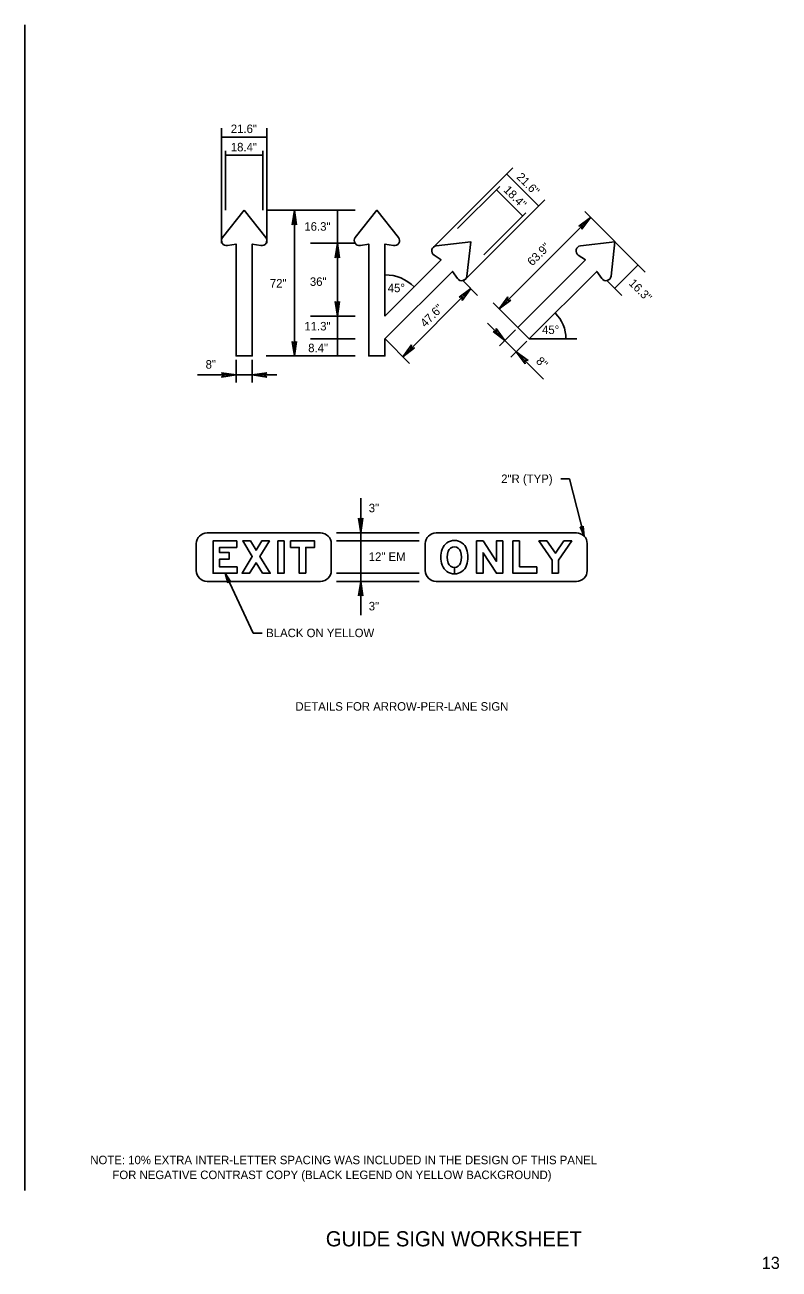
# Model space of a CAD drawing. Extents: x 531799 to 532094, y 1531149 to 1533620.
# Drawn here: x 531879.4 to 531932.2, y 1531151.4 to 1531238.5 of the extents above; entities that cross this region are included whole.
import ezdxf

# ---------------------------------------------------------------- set-up
doc = ezdxf.new("R2010")
doc.units = 0
for name, color, linetype in [('GSBWFill', 7, 'Continuous'), ('GSColorFill', 7, 'Continuous'), ('GSDims', 7, 'Continuous'), ('GSOutline', 7, 'Continuous'), ('LeaderLine_dp', 7, 'Continuous'), ('SheetBorder_dp', 7, 'Continuous'), ('SignPanel', 7, 'Continuous'), ('TextLabel', 7, 'Continuous'), ('TextMisc', 7, 'Continuous'), ('TextShtNo', 7, 'Continuous')]:
    doc.layers.add(name, color=color, linetype=linetype)

msp = doc.modelspace()

# ---------------------------------------------------------------- linework, layer by layer
at = {"layer": 'GSBWFill'}
for p, q in [((531892.157, 1531202.947), (531900.088, 1531202.947)), ((531917.996, 1531202.947), (531908.176, 1531202.947)), ((531891.401, 1531200.304), (531891.401, 1531202.192)), ((531900.844, 1531202.192), (531900.844, 1531200.304)), ((531907.421, 1531202.192), (531907.421, 1531200.304)), ((531918.751, 1531200.304), (531918.751, 1531202.192)), ((531909.458, 1531200.075), (531909.458, 1531200.528)), ((531909.458, 1531200.528), (531909.458, 1531200.075)), ((531900.088, 1531199.548), (531892.157, 1531199.548)), ((531908.176, 1531199.548), (531917.996, 1531199.548))]:
    msp.add_line(p, q, dxfattribs=at)
for points in [[(531894.227, 1531202.381), (531894.227, 1531201.928), (531893.026, 1531201.928), (531893.026, 1531201.565), (531893.705, 1531201.565), (531893.705, 1531201.112), (531893.026, 1531201.112), (531893.026, 1531200.568), (531894.249, 1531200.568), (531894.249, 1531200.115), (531892.572, 1531200.115), (531892.572, 1531202.381)], [(531896.039, 1531200.115), (531895.584, 1531200.859), (531895.129, 1531200.115), (531894.598, 1531200.115), (531895.319, 1531201.294), (531894.655, 1531202.381), (531895.186, 1531202.381), (531895.584, 1531201.729), (531895.982, 1531202.381), (531896.513, 1531202.381), (531895.85, 1531201.294), (531896.57, 1531200.115)], [(531897.094, 1531202.381), (531897.547, 1531202.381), (531897.547, 1531200.115), (531897.094, 1531200.115)], [(531899.061, 1531200.115), (531898.608, 1531200.115), (531898.608, 1531201.928), (531897.996, 1531201.928), (531897.996, 1531202.381), (531899.673, 1531202.381), (531899.673, 1531201.928), (531899.061, 1531201.928)], [(531911.012, 1531202.381), (531911.465, 1531202.381), (531912.394, 1531200.953), (531912.394, 1531202.381), (531912.847, 1531202.381), (531912.847, 1531200.115), (531912.399, 1531200.115), (531911.465, 1531201.55), (531911.465, 1531200.115), (531911.012, 1531200.115)], [(531914.003, 1531200.568), (531915.226, 1531200.568), (531915.226, 1531200.115), (531913.549, 1531200.115), (531913.549, 1531202.381), (531914.003, 1531202.381)], [(531916.748, 1531200.115), (531916.295, 1531200.115), (531916.295, 1531201.044), (531915.377, 1531202.381), (531915.926, 1531202.381), (531916.521, 1531201.515), (531917.116, 1531202.381), (531917.666, 1531202.381), (531916.748, 1531201.044)]]:
    msp.add_lwpolyline(points, close=True, dxfattribs=at)
for centre, radius, start, end in [((531892.157, 1531202.192), 0.755, 90, 180), ((531900.088, 1531202.192), 0.755, 0, 90), ((531908.176, 1531202.192), 0.755, 90, 180), ((531917.996, 1531202.192), 0.755, 0, 90), ((531909.458, 1531201.506), 0.906, 19.60625, 160.39375), ((531910.195, 1531201.244), 1.688, 160.39375, 199.60625), ((531910.195, 1531201.244), 1.235, 160.39375, 199.60625), ((531909.458, 1531201.506), 0.453, 19.60625, 160.39375), ((531908.722, 1531201.244), 1.235, 340.39375, 19.60625), ((531908.722, 1531201.244), 1.688, 340.39375, 19.60625), ((531892.157, 1531200.304), 0.755, 180, 270), ((531900.088, 1531200.304), 0.755, 270, 0), ((531908.176, 1531200.304), 0.755, 180, 270), ((531909.458, 1531200.982), 0.906, 199.60625, 270), ((531909.458, 1531200.982), 0.453, 199.60625, 270), ((531909.458, 1531200.982), 0.453, 270.01433, 340.39375), ((531909.458, 1531200.982), 0.906, 270.00716, 340.39375), ((531917.996, 1531200.304), 0.755, 270, 0)]:
    msp.add_arc(centre, radius, start, end, dxfattribs=at)
at = {"layer": 'GSColorFill'}
for p, q in [((531909.458, 1531200.075), (531909.458, 1531200.528)), ((531909.458, 1531200.528), (531909.458, 1531200.075))]:
    msp.add_line(p, q, dxfattribs=at)
for points in [[(531894.227, 1531202.381), (531894.227, 1531201.928), (531893.026, 1531201.928), (531893.026, 1531201.565), (531893.705, 1531201.565), (531893.705, 1531201.112), (531893.026, 1531201.112), (531893.026, 1531200.568), (531894.249, 1531200.568), (531894.249, 1531200.115), (531892.572, 1531200.115), (531892.572, 1531202.381)], [(531896.039, 1531200.115), (531895.584, 1531200.859), (531895.129, 1531200.115), (531894.598, 1531200.115), (531895.319, 1531201.294), (531894.655, 1531202.381), (531895.186, 1531202.381), (531895.584, 1531201.729), (531895.982, 1531202.381), (531896.513, 1531202.381), (531895.85, 1531201.294), (531896.57, 1531200.115)], [(531897.094, 1531202.381), (531897.547, 1531202.381), (531897.547, 1531200.115), (531897.094, 1531200.115)], [(531899.061, 1531200.115), (531898.608, 1531200.115), (531898.608, 1531201.928), (531897.996, 1531201.928), (531897.996, 1531202.381), (531899.673, 1531202.381), (531899.673, 1531201.928), (531899.061, 1531201.928)], [(531911.012, 1531202.381), (531911.465, 1531202.381), (531912.394, 1531200.953), (531912.394, 1531202.381), (531912.847, 1531202.381), (531912.847, 1531200.115), (531912.399, 1531200.115), (531911.465, 1531201.55), (531911.465, 1531200.115), (531911.012, 1531200.115)], [(531914.003, 1531200.568), (531915.226, 1531200.568), (531915.226, 1531200.115), (531913.549, 1531200.115), (531913.549, 1531202.381), (531914.003, 1531202.381)], [(531916.748, 1531200.115), (531916.295, 1531200.115), (531916.295, 1531201.044), (531915.377, 1531202.381), (531915.926, 1531202.381), (531916.521, 1531201.515), (531917.116, 1531202.381), (531917.666, 1531202.381), (531916.748, 1531201.044)]]:
    msp.add_lwpolyline(points, close=True, dxfattribs=at)
for centre, radius, start, end in [((531909.458, 1531201.506), 0.906, 19.60625, 160.39375), ((531910.195, 1531201.244), 1.688, 160.39375, 199.60625), ((531910.195, 1531201.244), 1.235, 160.39375, 199.60625), ((531909.458, 1531201.506), 0.453, 19.60625, 160.39375), ((531908.722, 1531201.244), 1.235, 340.39375, 19.60625), ((531908.722, 1531201.244), 1.688, 340.39375, 19.60625), ((531909.458, 1531200.982), 0.906, 199.60625, 270), ((531909.458, 1531200.982), 0.453, 199.60625, 270), ((531909.458, 1531200.982), 0.453, 270.01433, 340.39375), ((531909.458, 1531200.982), 0.906, 270.00716, 340.39375)]:
    msp.add_arc(centre, radius, start, end, dxfattribs=at)
at = {"layer": 'GSOutline'}
for points in [[(531894.227, 1531202.381), (531894.227, 1531201.928), (531893.026, 1531201.928), (531893.026, 1531201.565), (531893.705, 1531201.565), (531893.705, 1531201.112), (531893.026, 1531201.112), (531893.026, 1531200.568), (531894.249, 1531200.568), (531894.249, 1531200.115), (531892.572, 1531200.115), (531892.572, 1531202.381)], [(531896.039, 1531200.115), (531895.584, 1531200.859), (531895.129, 1531200.115), (531894.598, 1531200.115), (531895.319, 1531201.294), (531894.655, 1531202.381), (531895.186, 1531202.381), (531895.584, 1531201.729), (531895.982, 1531202.381), (531896.513, 1531202.381), (531895.85, 1531201.294), (531896.57, 1531200.115)], [(531897.094, 1531202.381), (531897.547, 1531202.381), (531897.547, 1531200.115), (531897.094, 1531200.115)], [(531899.061, 1531200.115), (531898.608, 1531200.115), (531898.608, 1531201.928), (531897.996, 1531201.928), (531897.996, 1531202.381), (531899.673, 1531202.381), (531899.673, 1531201.928), (531899.061, 1531201.928)], [(531911.012, 1531202.381), (531911.465, 1531202.381), (531912.394, 1531200.953), (531912.394, 1531202.381), (531912.847, 1531202.381), (531912.847, 1531200.115), (531912.399, 1531200.115), (531911.465, 1531201.55), (531911.465, 1531200.115), (531911.012, 1531200.115)], [(531914.003, 1531200.568), (531915.226, 1531200.568), (531915.226, 1531200.115), (531913.549, 1531200.115), (531913.549, 1531202.381), (531914.003, 1531202.381)], [(531916.748, 1531200.115), (531916.295, 1531200.115), (531916.295, 1531201.044), (531915.377, 1531202.381), (531915.926, 1531202.381), (531916.521, 1531201.515), (531917.116, 1531202.381), (531917.666, 1531202.381), (531916.748, 1531201.044)]]:
    msp.add_lwpolyline(points, close=True, dxfattribs=at)
for centre, radius, start, end in [((531909.458, 1531201.506), 0.906, 19.60625, 160.39375), ((531910.195, 1531201.244), 1.688, 160.39375, 199.60625), ((531910.195, 1531201.244), 1.235, 160.39375, 199.60625), ((531909.458, 1531201.506), 0.453, 19.60625, 160.39375), ((531908.722, 1531201.244), 1.235, 340.39375, 19.60625), ((531908.722, 1531201.244), 1.688, 340.39375, 19.60625), ((531909.458, 1531200.982), 0.906, 199.60625, 340.39375), ((531909.458, 1531200.982), 0.453, 199.60625, 340.39375)]:
    msp.add_arc(centre, radius, start, end, dxfattribs=at)
at = {"layer": 'LeaderLine_dp'}
for p, q in [((531893.165, 1531223.222), (531893.165, 1531231.279)), ((531896.334, 1531223.222), (531896.334, 1531231.279)), ((531893.165, 1531230.656), (531896.334, 1531230.656)), ((531893.447, 1531225.53), (531893.447, 1531229.697)), ((531893.447, 1531229.376), (531896.053, 1531229.376)), ((531896.053, 1531225.53), (531896.053, 1531229.697)), ((531907.848, 1531222.811), (531913.545, 1531228.509)), ((531913.105, 1531228.068), (531915.346, 1531225.827)), ((531909.68, 1531224.245), (531912.626, 1531227.191)), ((531912.399, 1531226.964), (531914.241, 1531225.121)), ((531902.506, 1531225.53), (531896.334, 1531225.53)), ((531898.107, 1531224.511), (531898.26, 1531225.53)), ((531898.26, 1531215.333), (531898.26, 1531225.53)), ((531898.26, 1531225.53), (531898.413, 1531224.511)), ((531901.268, 1531223.222), (531901.268, 1531225.53)), ((531910.089, 1531220.57), (531915.787, 1531226.268)), ((531898.26, 1531224.715), (531898.107, 1531224.511)), ((531898.413, 1531224.511), (531898.26, 1531224.715)), ((531911.522, 1531222.402), (531914.468, 1531225.348)), ((531912.584, 1531218.633), (531918.984, 1531225.032)), ((531918.155, 1531224.419), (531918.984, 1531225.032)), ((531918.984, 1531225.032), (531918.371, 1531224.203)), ((531918.578, 1531225.438), (531922.811, 1531221.205)), ((531918.407, 1531224.455), (531918.155, 1531224.419)), ((531918.371, 1531224.203), (531918.407, 1531224.455)), ((531902.506, 1531223.222), (531899.393, 1531223.222)), ((531901.115, 1531222.202), (531901.268, 1531223.222)), ((531901.268, 1531218.123), (531901.268, 1531223.222)), ((531901.268, 1531223.222), (531901.421, 1531222.202)), ((531901.268, 1531222.406), (531901.115, 1531222.202)), ((531901.421, 1531222.202), (531901.268, 1531222.406)), ((531920.672, 1531220.079), (531922.305, 1531221.711)), ((531910.089, 1531220.57), (531911.086, 1531219.573)), ((531920.181, 1531220.57), (531921.178, 1531219.573)), ((531905.846, 1531215.28), (531910.613, 1531220.047)), ((531909.783, 1531219.434), (531910.613, 1531220.047)), ((531910.036, 1531219.47), (531909.783, 1531219.434)), ((531910.613, 1531220.047), (531910, 1531219.218)), ((531910, 1531219.218), (531910.036, 1531219.47)), ((531912.584, 1531218.633), (531913.197, 1531219.462)), ((531913.197, 1531219.462), (531913.161, 1531219.209)), ((531901.268, 1531218.123), (531901.115, 1531219.143)), ((531901.115, 1531219.143), (531901.268, 1531218.939)), ((531901.268, 1531218.939), (531901.421, 1531219.143)), ((531901.421, 1531219.143), (531901.268, 1531218.123)), ((531912.179, 1531219.038), (531913.894, 1531217.323)), ((531913.414, 1531219.246), (531912.584, 1531218.633)), ((531913.161, 1531219.209), (531913.414, 1531219.246)), ((531902.506, 1531218.123), (531899.393, 1531218.123)), ((531901.268, 1531215.333), (531901.268, 1531218.123)), ((531911.777, 1531217.631), (531912.989, 1531216.418)), ((531912.412, 1531216.995), (531912.16, 1531217.031)), ((531912.16, 1531217.031), (531912.989, 1531216.418)), ((531912.989, 1531216.418), (531912.376, 1531217.248)), ((531912.376, 1531217.248), (531912.412, 1531216.995)), ((531912.613, 1531216.042), (531913.733, 1531217.163)), ((531898.26, 1531215.333), (531898.107, 1531216.353)), ((531898.107, 1531216.353), (531898.26, 1531216.149)), ((531898.26, 1531216.149), (531898.413, 1531216.353)), ((531898.413, 1531216.353), (531898.26, 1531215.333)), ((531902.506, 1531216.521), (531899.393, 1531216.521)), ((531904.604, 1531216.522), (531906.319, 1531214.806)), ((531905.846, 1531215.28), (531906.458, 1531216.109)), ((531906.458, 1531216.109), (531906.422, 1531215.857)), ((531912.989, 1531216.418), (531913.79, 1531215.617)), ((531913.414, 1531215.241), (531914.534, 1531216.361)), ((531914.695, 1531216.522), (531918.025, 1531216.522)), ((531894.183, 1531213.465), (531894.183, 1531215.049)), ((531895.316, 1531213.465), (531895.316, 1531215.049)), ((531902.506, 1531215.333), (531896.279, 1531215.333)), ((531906.675, 1531215.893), (531905.846, 1531215.28)), ((531906.422, 1531215.857), (531906.675, 1531215.893)), ((531913.79, 1531215.617), (531915.692, 1531213.715)), ((531913.79, 1531215.617), (531914.403, 1531214.788)), ((531914.619, 1531215.004), (531913.79, 1531215.617)), ((531914.403, 1531214.788), (531914.367, 1531215.04)), ((531914.367, 1531215.04), (531914.619, 1531215.004)), ((531894.183, 1531213.997), (531891.493, 1531213.997)), ((531893.367, 1531213.997), (531893.163, 1531214.15)), ((531893.163, 1531214.15), (531894.183, 1531213.997)), ((531894.183, 1531213.997), (531893.163, 1531213.844)), ((531893.163, 1531213.844), (531893.367, 1531213.997)), ((531895.316, 1531213.997), (531894.183, 1531213.997)), ((531895.316, 1531213.997), (531896.336, 1531214.15)), ((531897.03, 1531213.997), (531895.316, 1531213.997)), ((531896.336, 1531213.844), (531895.316, 1531213.997)), ((531896.336, 1531214.15), (531896.132, 1531213.997)), ((531896.132, 1531213.997), (531896.336, 1531213.844)), ((531902.902, 1531205.367), (531902.902, 1531202.947)), ((531902.902, 1531202.947), (531902.749, 1531203.967)), ((531902.749, 1531203.967), (531902.902, 1531203.763)), ((531902.902, 1531203.763), (531903.055, 1531203.967)), ((531903.055, 1531203.967), (531902.902, 1531202.947)), ((531901.212, 1531202.947), (531906.993, 1531202.947)), ((531902.902, 1531202.947), (531902.902, 1531199.548)), ((531918.396, 1531203.253), (531918.264, 1531203.36)), ((531918.264, 1531203.36), (531918.53, 1531202.726)), ((531918.462, 1531203.41), (531918.396, 1531203.253)), ((531918.53, 1531202.726), (531918.462, 1531203.41)), ((531901.212, 1531202.381), (531906.993, 1531202.381)), ((531893.411, 1531200.115), (531893.793, 1531199.543)), ((531893.608, 1531199.456), (531893.411, 1531200.115)), ((531893.642, 1531199.623), (531893.608, 1531199.456)), ((531893.793, 1531199.543), (531893.642, 1531199.623)), ((531901.212, 1531200.115), (531906.993, 1531200.115)), ((531901.212, 1531199.548), (531906.993, 1531199.548)), ((531902.749, 1531198.528), (531902.902, 1531199.548)), ((531902.902, 1531199.548), (531902.902, 1531197.197)), ((531902.902, 1531199.548), (531903.055, 1531198.528)), ((531902.902, 1531198.732), (531902.749, 1531198.528)), ((531903.055, 1531198.528), (531902.902, 1531198.732))]:
    msp.add_line(p, q, dxfattribs=at)
for centre, radius, start, end in [((531904.603, 1531218.123), 2.884, 45, 90), ((531914.695, 1531216.522), 2.569, 360, 45)]:
    msp.add_arc(centre, radius, start, end, dxfattribs=at)
at = {"layer": 'SheetBorder_dp'}
msp.add_line((531879.408, 1531238.504), (531879.408, 1531156.924), dxfattribs=at)
at = {"layer": 'SignPanel'}
for p, q in [((531893.235, 1531223.627), (531894.75, 1531225.53)), ((531894.75, 1531225.53), (531896.264, 1531223.627))]:
    msp.add_line(p, q, dxfattribs=at)
for points in [[(531905.551, 1531223.627), (531904.036, 1531225.53), (531902.522, 1531223.627)], [(531895.908, 1531223.058), (531895.316, 1531223.166), (531895.316, 1531215.333), (531894.183, 1531215.333), (531894.183, 1531223.166), (531893.591, 1531223.058)], [(531902.878, 1531223.058), (531903.47, 1531223.166), (531903.47, 1531215.333), (531904.603, 1531215.333), (531904.603, 1531216.521), (531909.33, 1531221.248), (531909.672, 1531220.753)], [(531904.603, 1531218.123), (531904.603, 1531223.166), (531905.195, 1531223.058)], [(531910.327, 1531220.904), (531910.601, 1531223.321), (531908.185, 1531223.046)], [(531918.277, 1531223.046), (531920.693, 1531223.321), (531920.418, 1531220.904)], [(531908.034, 1531222.391), (531908.529, 1531222.049), (531904.603, 1531218.123)], [(531913.894, 1531217.323), (531918.621, 1531222.049), (531918.126, 1531222.391)], [(531919.764, 1531220.753), (531919.422, 1531221.248), (531914.695, 1531216.522), (531913.894, 1531217.323)]]:
    msp.add_lwpolyline(points, dxfattribs=at)
for centre, start, end in [((531893.526, 1531223.413), 143.69808, 280.32959), ((531895.973, 1531223.413), 259.67041, 36.30192), ((531902.813, 1531223.413), 143.69808, 280.32959), ((531905.259, 1531223.413), 259.67041, 36.30192), ((531908.24, 1531222.689), 98.69808, 235.32959), ((531918.331, 1531222.689), 98.69808, 235.32959), ((531909.969, 1531220.959), 214.67041, 351.30192), ((531920.061, 1531220.959), 214.67041, 351.30192)]:
    msp.add_arc(centre, 0.361, start, end, dxfattribs=at)
at = {"layer": 'TextLabel'}
for p, q in [((531916.896, 1531206.722), (531917.516, 1531206.722)), ((531918.53, 1531202.726), (531917.516, 1531206.722)), ((531893.411, 1531200.115), (531895.379, 1531195.933)), ((531895.999, 1531195.933), (531895.379, 1531195.933))]:
    msp.add_line(p, q, dxfattribs=at)

# ---------------------------------------------------------------- texts
at = {"layer": 'GSDims'}
for s, p in [('21.6"', (531893.812, 1531230.932)), ('18.4"', (531893.812, 1531229.652)), ('16.3"', (531898.961, 1531224.097)), ('72"', (531896.549, 1531220.12)), ('36"', (531899.346, 1531220.235)), ('45°', (531904.795, 1531219.795)), ('11.3"', (531898.961, 1531217.116)), ('45°', (531915.59, 1531216.865)), ('8.4"', (531899.228, 1531215.594)), ('8"', (531892.052, 1531214.442)), ('3"', (531903.464, 1531204.391)), ('12" EM', (531903.464, 1531200.985)), ('3"', (531903.464, 1531197.519))]:
    msp.add_text(s, height=0.595, dxfattribs=at).set_placement(p)
for s, rotation, p in [('21.6"', 315, (531913.757, 1531227.806)), ('18.4"', 315, (531912.852, 1531226.9)), ('63.9"', 45, (531914.909, 1531221.591)), ('16.3"', 315, (531921.618, 1531220.372)), ('47.6"', 45, (531907.424, 1531217.296)), ('8"', 315, (531915.121, 1531214.915))]:
    msp.add_text(s, height=0.595, rotation=rotation, dxfattribs=at).set_placement(p)
at = {"layer": 'TextLabel'}
msp.add_text('2"R (TYP)', height=0.595, rotation=360, dxfattribs=at).set_placement((531912.732, 1531206.436))
for s, p in [('BLACK ON YELLOW', (531896.288, 1531195.647)), ('DETAILS FOR ARROW-PER-LANE SIGN', (531898.338, 1531190.5)), ('NOTE: 10% EXTRA INTER-LETTER SPACING WAS INCLUDED IN THE DESIGN OF THIS PANEL', (531883.982, 1531158.753)), ('       FOR NEGATIVE CONTRAST COPY (BLACK LEGEND ON YELLOW BACKGROUND)', (531883.982, 1531157.712))]:
    msp.add_text(s, height=0.595, dxfattribs=at).set_placement(p)
at = {"layer": 'TextMisc'}
msp.add_text('     GUIDE SIGN WORKSHEET      ', height=1.0625, rotation=360, dxfattribs=at).set_placement((531898.487, 1531153.001))
at = {"layer": 'TextShtNo'}
msp.add_text('13', height=0.85, rotation=360, dxfattribs=at).set_placement((531930.962, 1531151.423))

doc.saveas('drawing.dxf')
